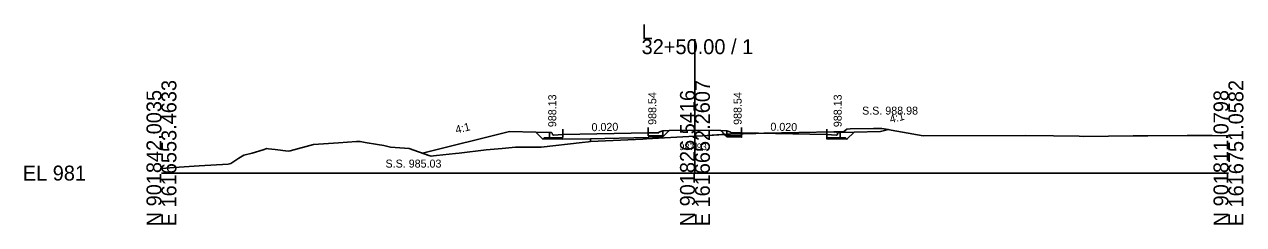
# Model space of a CAD drawing. Extents: x 1009 to 7438, y -1586 to 7964.
# Drawn here: x 3009.2 to 3237.7, y 414 to 451.7 of the extents above; entities that cross this region are included whole.
import ezdxf

# ---------------------------------------------------------------- set-up
doc = ezdxf.new("R2010")
doc.units = 0
for name, color, linetype in [('Exist Cross Section Cell', 7, 'Continuous'), ('Exist XS Center Line Elevation Label', 7, 'Continuous'), ('Exist XS Ground Line', 7, 'Continuous'), ('Prop XS Dump Level', 7, 'Continuous'), ('Prop XS Earthwork Shape', 7, 'Continuous'), ('Prop XS EOT Tick Mark', 7, 'Continuous'), ('Prop XS Finish Grade', 7, 'Continuous'), ('Prop XS Finish Grade CurbGutter', 7, 'Continuous'), ('Prop XS Finish Grade Earthwork', 7, 'Continuous'), ('Prop XS Finish Grade Pavement', 7, 'Continuous'), ('Prop XS Hydro Elevations', 7, 'Continuous'), ('Prop XS Pvmt Edge Slope', 7, 'Continuous'), ('Prop XS SE Text', 7, 'Continuous'), ('Prop XS Side Slope Text', 7, 'Continuous'), ('Prop XS SS Elevation Text', 7, 'Continuous'), ('Prop XS Subgrade CurbGutter', 7, 'Continuous'), ('Prop XS Subgrade Earthwork', 7, 'Continuous')]:
    doc.layers.add(name, color=color, linetype=linetype)

msp = doc.modelspace()

# ---------------------------------------------------------------- linework, layer by layer
at = {"layer": 'Exist Cross Section Cell'}
for p, q in [((3134.89, 423.73), (3134.89, 448.87)), ((3034.89, 423.73), (3134.89, 423.73)), ((3134.89, 423.73), (3234.89, 423.73))]:
    msp.add_line(p, q, dxfattribs=at)
at = {"layer": 'Exist XS Ground Line'}
for p, q in [((3162.73, 431.49), (3163.39, 432)), ((3163.39, 432), (3163.99, 432.01)), ((3163.99, 432.01), (3168.38, 432.1)), ((3168.38, 432.1), (3168.86, 432.1)), ((3168.86, 432.1), (3169.91, 432.11)), ((3169.91, 432.11), (3177.66, 430.75)), ((3068.07, 429.39), (3071.45, 429.69)), ((3071.45, 429.69), (3072.12, 429.63)), ((3114.93, 429.61), (3115.32, 429.66)), ((3115.32, 429.66), (3116.74, 429.73)), ((3116.74, 429.73), (3125.1, 430.11)), ((3125.1, 430.11), (3125.82, 430.15)), ((3125.82, 430.15), (3134.89, 430.66)), ((3134.89, 430.66), (3136.32, 430.74)), ((3136.32, 430.74), (3140.8, 431.01)), ((3140.8, 431.01), (3141.15, 431.03)), ((3141.15, 431.03), (3141.53, 431.04)), ((3141.53, 431.04), (3146.33, 431.17)), ((3146.33, 431.17), (3147.8, 431.2)), ((3147.8, 431.2), (3160.94, 431.47)), ((3160.94, 431.47), (3162.73, 431.49)), ((3177.66, 430.75), (3196.79, 430.78)), ((3196.79, 430.78), (3202.07, 430.7)), ((3202.07, 430.7), (3206.91, 430.64)), ((3206.91, 430.64), (3207.81, 430.63)), ((3207.81, 430.63), (3217.03, 430.71)), ((3217.03, 430.71), (3219.81, 430.73)), ((3219.81, 430.73), (3227.16, 430.81)), ((3227.16, 430.81), (3231.81, 430.76)), ((3231.81, 430.76), (3234.89, 430.71)), ((3050.32, 427.09), (3051.92, 427.48)), ((3051.92, 427.48), (3053.95, 428.11)), ((3053.95, 428.11), (3054.66, 428.34)), ((3054.66, 428.34), (3054.97, 428.29)), ((3054.97, 428.29), (3056.19, 428.15)), ((3056.19, 428.15), (3058.64, 427.83)), ((3058.64, 427.83), (3059.03, 427.92)), ((3059.03, 427.92), (3063.37, 429.11)), ((3063.37, 429.11), (3068.07, 429.39)), ((3072.12, 429.63), (3073.05, 429.47)), ((3073.05, 429.47), (3075.37, 429.08)), ((3075.37, 429.08), (3076.59, 428.88)), ((3076.59, 428.88), (3077.84, 428.59)), ((3077.84, 428.59), (3079.6, 428.45)), ((3079.6, 428.45), (3081.34, 428.32)), ((3081.34, 428.32), (3085, 427.05)), ((3086.44, 427), (3090.02, 427.38)), ((3090.02, 427.38), (3090.72, 427.46)), ((3090.72, 427.46), (3095.73, 428.1)), ((3095.73, 428.1), (3098.76, 428.37)), ((3098.76, 428.37), (3101.26, 428.57)), ((3101.26, 428.57), (3102.91, 428.57)), ((3102.91, 428.57), (3106.07, 428.57)), ((3106.07, 428.57), (3113.74, 429.47)), ((3113.74, 429.47), (3114.93, 429.61)), ((3037.28, 424.78), (3041.97, 425.08)), ((3041.97, 425.08), (3047.39, 425.43)), ((3047.39, 425.43), (3047.91, 425.55)), ((3047.91, 425.55), (3049.4, 426.51)), ((3049.4, 426.51), (3050.32, 427.09)), ((3085, 427.05), (3085.46, 426.9)), ((3085.46, 426.9), (3085.88, 426.94)), ((3085.88, 426.94), (3086.44, 427)), ((3034.89, 424.61), (3037.28, 424.78))]:
    msp.add_line(p, q, dxfattribs=at)
at = {"layer": 'Prop XS Dump Level'}
for p, q in [((3110.14, 430.98), (3126.14, 431.3)), ((3110.14, 430.98), (3126.14, 431.3)), ((3143.64, 431.3), (3159.64, 430.98)), ((3143.64, 431.3), (3159.64, 430.98))]:
    msp.add_line(p, q, dxfattribs=at)
at = {"layer": 'Prop XS Earthwork Shape'}
for points in [[(3162.14, 431.36), (3161.89, 431.36), (3161.77, 431.33), (3161.68, 431.24), (3161.61, 430.99), (3161.52, 430.9), (3161.39, 430.88), (3159.64, 430.98), (3159.64, 431.44), (3160.94, 431.47), (3162.73, 431.49), (3163.39, 432), (3163.99, 432.01), (3168.38, 432.1), (3168.86, 432.1), (3169.91, 432.11), (3171.14, 431.9), (3169.64, 431.52), (3164.73, 431.42)], [(3102.91, 428.57), (3106.07, 428.57), (3113.74, 429.47), (3114.93, 429.61), (3115.32, 429.66), (3115.32, 430.17), (3110.14, 430.07), (3110.14, 430.15), (3106.39, 430.08), (3105.05, 431.42), (3100.14, 431.52), (3083.85, 427.45), (3085, 427.05), (3085.46, 426.9), (3085.88, 426.94), (3086.44, 427), (3090.02, 427.38), (3090.72, 427.46), (3095.73, 428.1), (3098.76, 428.37), (3101.26, 428.57)], [(3125.1, 430.11), (3125.82, 430.15), (3134.89, 430.66), (3136.32, 430.74), (3140.44, 430.99), (3139.72, 431.71), (3139.67, 431.71), (3134.89, 431.81), (3130.12, 431.71), (3130.07, 431.71), (3128.89, 430.53), (3126.14, 430.47), (3126.14, 430.39), (3115.32, 430.17), (3115.32, 429.66), (3116.74, 429.73)], [(3141.14, 430.77), (3140.9, 430.53), (3140.44, 430.99), (3140.8, 431.01), (3140.89, 431.02), (3140.89, 430.78)], [(3143.64, 430.72), (3143.64, 431.1), (3141.53, 431.04), (3141.15, 431.03), (3140.89, 431.02), (3140.89, 430.78), (3141.14, 430.77), (3142.14, 430.75)], [(3141.14, 430.77), (3140.9, 430.53), (3143.64, 430.47), (3143.64, 430.72), (3142.14, 430.75)], [(3162.14, 431.36), (3161.89, 431.36), (3161.77, 431.33), (3161.68, 431.24), (3161.61, 430.99), (3161.52, 430.9), (3161.39, 430.88), (3159.64, 430.98), (3159.64, 430.4), (3162.14, 430.35)], [(3159.64, 430.15), (3159.64, 430.4), (3162.14, 430.35), (3163.14, 430.33), (3163.39, 430.08)], [(3163.39, 430.08), (3164.73, 431.42), (3162.14, 431.36), (3162.14, 430.35), (3163.14, 430.33)]]:
    msp.add_lwpolyline(points, close=True, dxfattribs=at)
at = {"layer": 'Prop XS EOT Tick Mark'}
for p, q in [((3110.14, 430.98), (3110.14, 431.98)), ((3126.14, 431.3), (3126.14, 432.3)), ((3143.64, 431.3), (3143.64, 432.3)), ((3159.64, 430.98), (3159.64, 431.98))]:
    msp.add_line(p, q, dxfattribs=at)
at = {"layer": 'Prop XS Finish Grade'}
for p, q in [((3107.64, 431.36), (3105.05, 431.42)), ((3128.89, 431.68), (3130.12, 431.71)), ((3140.89, 431.68), (3139.67, 431.71)), ((3162.14, 431.36), (3164.73, 431.42))]:
    msp.add_line(p, q, dxfattribs=at)
at = {"layer": 'Prop XS Finish Grade CurbGutter'}
for p, q in [((3107.64, 431.36), (3107.89, 431.36)), ((3107.89, 431.36), (3108.02, 431.33)), ((3108.11, 431.24), (3108.02, 431.33)), ((3108.18, 430.99), (3108.11, 431.24)), ((3108.27, 430.9), (3108.18, 430.99)), ((3108.39, 430.88), (3108.27, 430.9)), ((3110.14, 430.98), (3108.39, 430.88)), ((3126.14, 431.3), (3126.89, 431.29)), ((3126.14, 431.3), (3128.14, 431.26)), ((3128.14, 431.43), (3128.89, 431.68)), ((3128.14, 431.26), (3128.14, 431.43)), ((3141.64, 431.43), (3140.89, 431.68)), ((3141.64, 431.26), (3141.64, 431.43)), ((3143.64, 431.3), (3141.64, 431.26)), ((3143.64, 431.3), (3142.89, 431.29)), ((3159.64, 430.98), (3161.39, 430.88)), ((3161.39, 430.88), (3161.52, 430.9)), ((3161.52, 430.9), (3161.61, 430.99)), ((3161.61, 430.99), (3161.68, 431.24)), ((3161.68, 431.24), (3161.77, 431.33)), ((3161.89, 431.36), (3161.77, 431.33)), ((3162.14, 431.36), (3161.89, 431.36))]:
    msp.add_line(p, q, dxfattribs=at)
at = {"layer": 'Prop XS Finish Grade Earthwork'}
for p, q in [((3100.14, 431.52), (3083.85, 427.45)), ((3105.05, 431.42), (3100.14, 431.52)), ((3130.12, 431.71), (3134.89, 431.81)), ((3134.89, 431.81), (3139.67, 431.71)), ((3164.73, 431.42), (3169.64, 431.52)), ((3169.64, 431.52), (3171.14, 431.9))]:
    msp.add_line(p, q, dxfattribs=at)
at = {"layer": 'Prop XS Finish Grade Pavement'}
for p, q in [((3110.14, 430.98), (3126.14, 431.3)), ((3143.64, 431.3), (3159.64, 430.98))]:
    msp.add_line(p, q, dxfattribs=at)
at = {"layer": 'Prop XS Pvmt Edge Slope'}
for p, q in [((3106.64, 430.33), (3106.39, 430.08)), ((3107.64, 430.35), (3106.64, 430.33)), ((3127.64, 430.75), (3128.89, 430.78)), ((3127.64, 430.75), (3128.64, 430.77)), ((3128.64, 430.77), (3128.89, 430.53)), ((3142.14, 430.75), (3140.89, 430.78)), ((3141.14, 430.77), (3140.9, 430.53)), ((3142.14, 430.75), (3141.14, 430.77)), ((3162.14, 430.35), (3163.14, 430.33)), ((3163.14, 430.33), (3163.39, 430.08))]:
    msp.add_line(p, q, dxfattribs=at)
at = {"layer": 'Prop XS Subgrade CurbGutter'}
for p, q in [((3107.64, 430.35), (3107.64, 431.36)), ((3110.14, 430.4), (3107.64, 430.35)), ((3110.14, 430.98), (3110.14, 430.4)), ((3126.14, 431.3), (3126.14, 430.72)), ((3126.14, 430.72), (3127.64, 430.75)), ((3128.89, 430.78), (3128.89, 431.68)), ((3140.89, 430.78), (3140.89, 431.68)), ((3143.64, 430.72), (3142.14, 430.75)), ((3143.64, 431.3), (3143.64, 430.72)), ((3159.64, 430.98), (3159.64, 430.4)), ((3159.64, 430.4), (3162.14, 430.35)), ((3162.14, 430.35), (3162.14, 431.36))]:
    msp.add_line(p, q, dxfattribs=at)
at = {"layer": 'Prop XS Subgrade Earthwork'}
for p, q in [((3106.39, 430.08), (3105.05, 431.42)), ((3110.14, 430.15), (3106.39, 430.08)), ((3115.32, 430.17), (3110.14, 430.07)), ((3110.14, 430.07), (3110.14, 430.15)), ((3115.32, 430.17), (3126.14, 430.39)), ((3126.14, 430.47), (3128.89, 430.53)), ((3126.14, 430.39), (3126.14, 430.47)), ((3128.89, 430.53), (3130.07, 431.71)), ((3140.9, 430.53), (3139.72, 431.71)), ((3143.64, 430.47), (3140.9, 430.53)), ((3143.64, 430.39), (3143.64, 431.1)), ((3143.64, 430.39), (3143.64, 430.47)), ((3159.64, 430.07), (3159.64, 431.44)), ((3159.64, 430.07), (3159.64, 430.15)), ((3159.64, 430.15), (3163.39, 430.08)), ((3163.39, 430.08), (3164.73, 431.42))]:
    msp.add_line(p, q, dxfattribs=at)

# ---------------------------------------------------------------- texts
at = {"layer": 'Exist Cross Section Cell'}
for s, p in [('L', (3124.89, 448.87)), ('32+50.00 / 1', (3124.89, 446.07)), ('EL 981', (3008.89, 422.33))]:
    msp.add_text(s, height=2.8, dxfattribs=at).set_placement(p)
for s, p in [('N 901842.0035', (3034.89, 413.73)), ('E 1616553.4633', (3037.69, 413.73)), ('N 901826.5416', (3134.89, 413.73)), ('E 1616652.2607', (3137.69, 413.73)), ('N 901811.0798', (3234.89, 413.73)), ('E 1616751.0582', (3237.69, 413.73))]:
    msp.add_text(s, height=2.8, rotation=90, dxfattribs=at).set_placement(p)
at = {"layer": 'Exist XS Center Line Elevation Label'}
msp.add_text('987.93', height=1.25, dxfattribs=at).set_placement((3131.99, 428.04))
at = {"layer": 'Prop XS Dump Level'}
msp.add_text('Eop', height=0.3, dxfattribs=at).set_placement((3160.94, 431.17))
at = {"layer": 'Prop XS Hydro Elevations'}
for s, p in [('988.54', (3127.64, 432.79)), ('988.54', (3143.64, 432.79)), ('988.13', (3108.89, 432.36)), ('988.13', (3162.39, 432.36))]:
    msp.add_text(s, height=1.5, rotation=90, dxfattribs=at).set_placement(p)
at = {"layer": 'Prop XS SE Text'}
for rotation, p in [(1.1458, (3115.52, 431.59)), (358.8542, (3149.02, 431.7))]:
    msp.add_text('0.020', height=1.5, rotation=rotation, dxfattribs=at).set_placement(p)
at = {"layer": 'Prop XS Side Slope Text'}
for p in [(3171.57, 433.09), (3090.18, 431.12)]:
    msp.add_text('4:1', height=1.5, rotation=14.0362, dxfattribs=at).set_placement(p)
at = {"layer": 'Prop XS SS Elevation Text'}
for s, p in [('S.S. 988.98', (3166.22, 434.71)), ('S.S. 985.03', (3076.89, 424.76))]:
    msp.add_text(s, height=1.5, dxfattribs=at).set_placement(p)

doc.saveas('drawing.dxf')
